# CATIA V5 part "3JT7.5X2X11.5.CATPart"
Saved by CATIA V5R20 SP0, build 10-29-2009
Part number: 3JT7.5X2X11.5
Revision: ANY
Definition: UNKNOWN
Nomenclature: 3JT7.5X2X11.5
Source: Unknown
Bounding box of the stored display mesh (mm): x -5.75 to 5.75, y -5.75 to 5.75, z -1 to 1
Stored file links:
  C:\Users\Utente\Desktop\IO LAVORO\3D X SITO CF\CUMSA\3D files PW\pw060822\pw060822_ejection\3JT7.5X2X11.5.CATPart
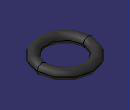
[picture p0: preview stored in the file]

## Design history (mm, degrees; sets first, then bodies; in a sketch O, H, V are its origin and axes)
Body1 "Revolución1" (main body)
  Solid1: solid without history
